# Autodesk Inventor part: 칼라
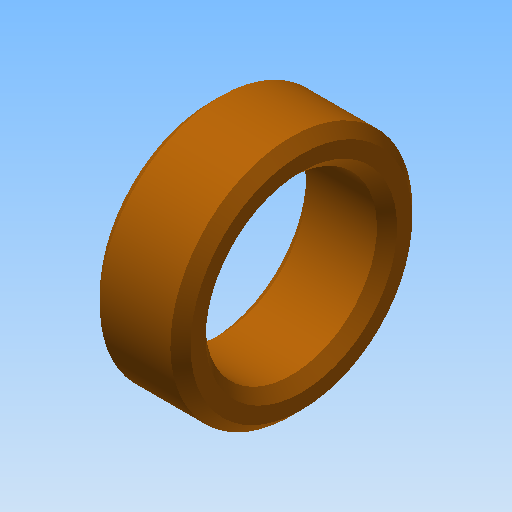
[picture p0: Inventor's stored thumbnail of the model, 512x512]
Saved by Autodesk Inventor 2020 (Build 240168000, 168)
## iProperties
Created: 2016-10
Part Number: 칼라
Material: 강철, 연강
Document SubType Name: Modeling
Designer: mduedu
Density: 1 g/cm^3
Appearance: 주황색
Author: mduedu
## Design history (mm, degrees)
sketch "스케치1"
  geometry: C1 r 12 at (0, 0); C2 r 8.5 at (0, 0); 1 further point
  constraints: 2 centre point, 2 coincident
  dimensions: "d0" = 24 diameter of C1; "d1" = 17 diameter of C2
extrude "돌출1" new body sketch "스케치1" distance "d2" = 9; taper "d3" = 0 deg
chamfer "모따기1" distance "d4" = 1; stored, may be unused: second distance "d5" = 2, angle "d6" = 45 deg
node "솔리드1"
